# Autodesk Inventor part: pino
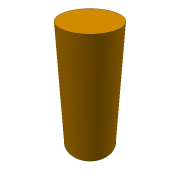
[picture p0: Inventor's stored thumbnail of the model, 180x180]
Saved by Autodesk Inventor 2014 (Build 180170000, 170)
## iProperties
Created: 2012-09
Part Number: pino
Material: Aço forjado
Document SubType Name: Modeling
Designer: TR-06
Density: 1 g/cm^3
Mass: 3.68155 g
Surface Area: 14.2353 cm^2
Volume: 3.68155 cm^3
Appearance: Steel
Author: TR-06
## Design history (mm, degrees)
sketch "Sketch1"
  geometry: C1 r 6.25 at (0, 0); 1 further point
  constraints: 1 centre point, 1 coincident
  dimensions: "d0" = 12.5 diameter of C1
extrude "Extrusion1" new body sketch "Sketch1" distance "d1" = 30; taper "d2" = 0 deg
body "Solid1"
